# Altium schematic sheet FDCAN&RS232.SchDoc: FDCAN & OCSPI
size A4; Date: Not used; ApprovedBy: Not used; CheckedBy: Not used; Author: Not used; CompanyName: STMicroelectronics; DrawnBy: Not used; Engineer: Not used; Organization: Not used; Address1: Not used; Address2: Not used; Address3: Not used; Address4: Not used; DocumentNumber: Not used; Revision: Not used; SheetNumber: 15; SheetTotal: 23
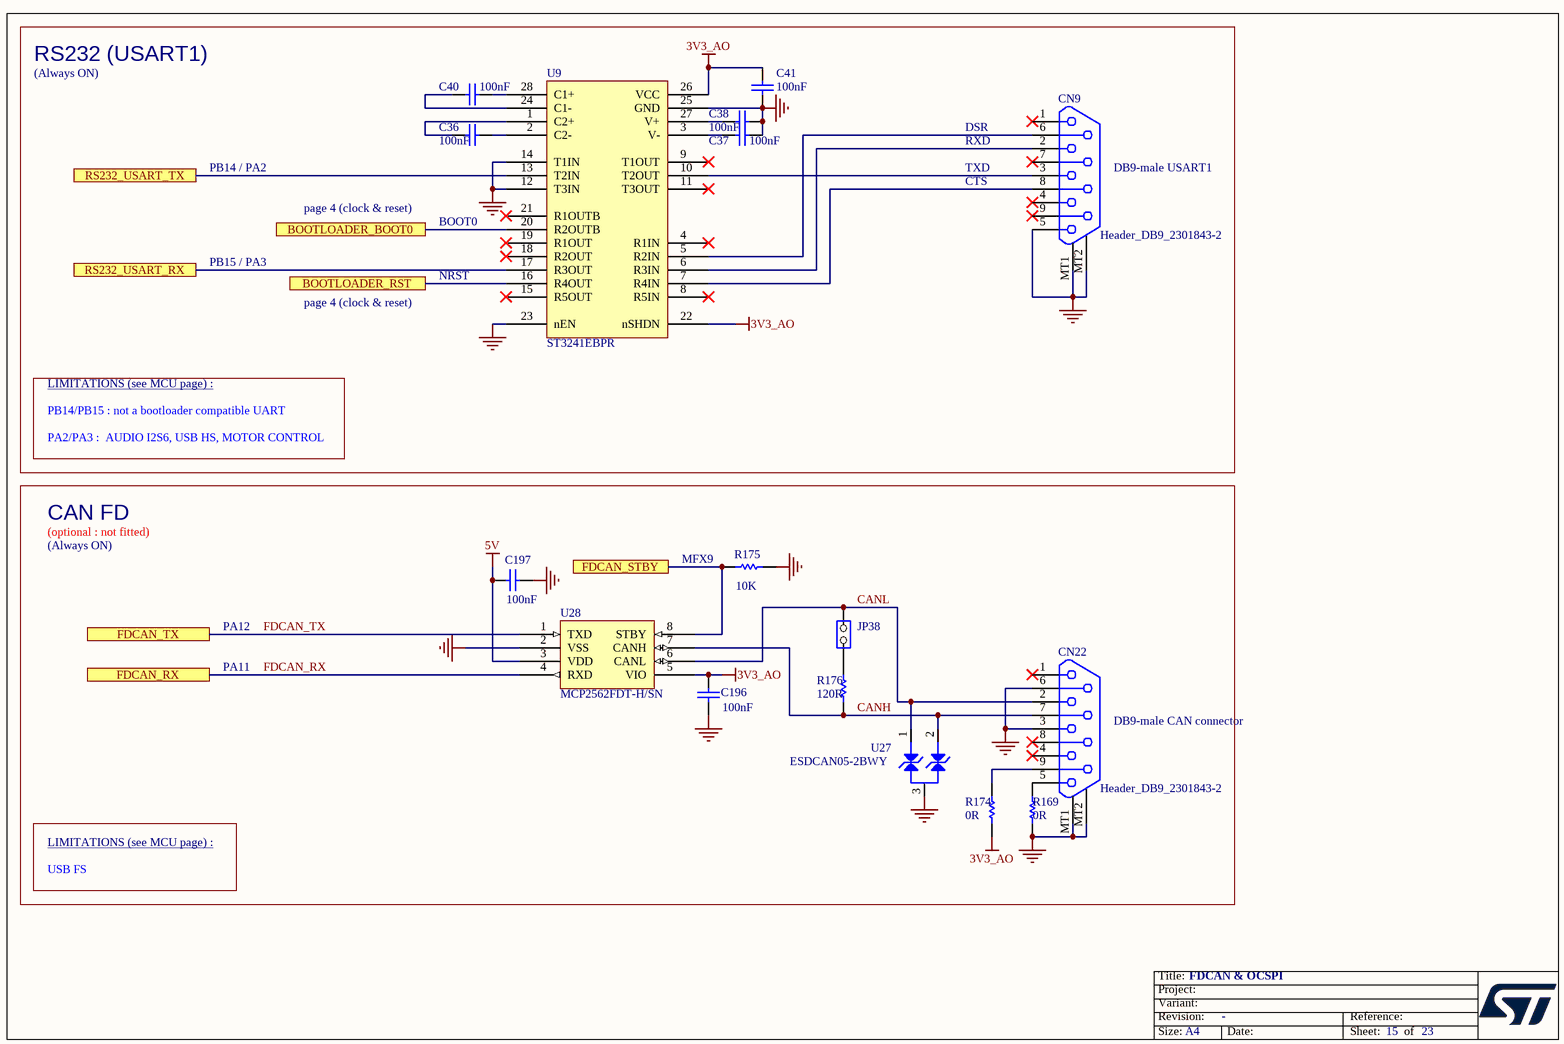
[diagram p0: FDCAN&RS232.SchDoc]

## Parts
C36  value 100nF  [C0402]  (hidden comment: Capacitor)
C37  value 100nF  [C0402]  (hidden comment: Capacitor)
C38  value 100nF  [C0402]  (hidden comment: Capacitor)
C40  value 100nF  [C0402]  (hidden comment: Capacitor)
C41  value 100nF  [C0402]  (hidden comment: Capacitor)
C196  value 100nF  [C0402]  (hidden comment: Capacitor)
C197  value 100nF  [C0402]  (hidden comment: Capacitor)
CN9  value Header_DB9_2301843-2  [CON_DB9-MALE_TYCO_2301843-2]  (hidden comment: DB9_Header_male_2301843-2)
CN22  value Header_DB9_2301843-2  [CON_DB9-MALE_TYCO_2301843-2]  (hidden comment: DB9_Header_male_2301843-2)
JP38  Jumper_Header 2x1  [CON_SAMTEC_TSW-102-07-G-S]  (value not drawn)
R169  value 0R  [R0603]  (hidden comment: Resistor)
R174  value 0R  [R0603]  (hidden comment: Resistor)
R175  value 10K  [R0402]  (hidden comment: Resistor)
R176  value 120R  [R0402]  (hidden comment: Resistor)
U9  ST3241EBPR  [ICC_SSOP28_10P2X5P3_P065]
U27  value ESDCAN05-2BWY  [DIO_SOT323]  (hidden comment: ESD-TRANSIL-DUAL-BIDIR)
U28  value MCP2562FDT-H/SN  [ICC_SO8_5X4_P127]  (hidden comment: MCP2562FD)

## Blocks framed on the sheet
RS232 (USART1): C36-C38 C40 C41 CN9 U9
CAN FD: C196 C197 CN22 JP38 R169 R174-R176 U27 U28

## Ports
BOOTLOADER_BOOT0, BOOTLOADER_RST, FDCAN_RX, FDCAN_STBY, FDCAN_TX, RS232_USART_RX, RS232_USART_TX

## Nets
3V3_AO: C41.1 C196.1 R174.1 U9.22(nSHDN) U9.26(VCC) U28.5(VIO)
5V: C197.1 U28.3(VDD)
GND: C37.1 C38.1 C41.2 C196.2 C197.2 CN9.5 CN9.MT1 CN9.MT2 CN22.3 CN22.6 CN22.MT1 CN22.MT2 R169.1 R175.2 U9.12(T3IN) U9.14(T1IN) U9.23(nEN) U9.25(GND) U27.3 U28.2(VSS)
BOOTLOADER_BOOT0: U9.20(R2OUTB) ; port BOOTLOADER_BOOT0
BOOTLOADER_RST: U9.16(R4OUT) ; port BOOTLOADER_RST
CANH: CN22.7 R176.1 U27.2 U28.7(CANH)
CANL: CN22.2 JP38.2(NO) U27.1 U28.6(CANL)
FDCAN_RX: U28.4(RXD) ; port FDCAN_RX
FDCAN_STBY: R175.1 U28.8(STBY) ; port FDCAN_STBY
FDCAN_TX: U28.1(TXD) ; port FDCAN_TX
RS232_USART_RX: U9.17(R3OUT) ; port RS232_USART_RX
RS232_USART_TX: U9.13(T2IN) ; port RS232_USART_TX
NetC36_1: C36.1 U9.1(C2+)
NetC36_2: C36.2 U9.2(C2-)
NetC37_2: C37.2 U9.3(V-)
NetC38_2: C38.2 U9.27(V+)
NetC40_1: C40.1 U9.24(C1-)
NetC40_2: C40.2 U9.28(C1+)
NetCN9_2: CN9.2 U9.6(R3IN)
NetCN9_3: CN9.3 U9.10(T2OUT)
NetCN9_6: CN9.6 U9.5(R2IN)
NetCN9_8: CN9.8 U9.7(R4IN)
NetCN22_5: CN22.5 R169.2
NetCN22_9: CN22.9 R174.2
NetJP38_1: JP38.1(COMMON) R176.2

Not connected (* = marked no-connect by the designer): CN9 1* 4* 7* 9*; CN22 1* 4* 8*; U9 4(R1IN)* 8(R5IN)* 9(T1OUT)* 11(T3OUT)* 15(R5OUT)* 18(R2OUT)* 19(R1OUT)* 21(R1OUTB)*

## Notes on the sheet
- (Always ON)
- PB14 / PA2
- RXD
- TXD
- CTS
- DSR
- (near CN9) DB9-male USART1
- page 4 (clock & reset)
- BOOT0
- PB15 / PA3
- NRST
- LIMITATIONS (see MCU page) :
- PB14/PB15 : not a bootloader compatible UART
- PA2/PA3 :  AUDIO I2S6, USB HS, MOTOR CONTROL
- (optional : not fitted)
- (near R175) MFX9
- PA12
- PA11
- (near CN22) DB9-male CAN connector
- USB FS

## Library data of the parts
C36-C38 C40 C41 C196 C197 = MCD-00006: Capacitor, MLCC, 100nF, 16V, X7R, 10%, 0402, T=0.5mm; Manufacturer_Part_Number: CC0402KRX7R7BB104; Manufacturer: YAGEO; Alternate_Manufacturer_Part_Number: GCM155R71C104KA55D; Alternate_Manufacturer: MURATA; Part_Preference: Recommended; Partial_Alternate_Internal_Part_Number: MCD-03299; Provided_By: SUBCO; ECCN_US: EAR99; ECCN_EU: NEC; Component_Country_Of_Origin: China; ID: 2474; Order_Code_RS: 9402047; ShowFields: YES
CN9 CN22 = MCD-01978: DB9_Male, RA, TH, height 13.575mm/3.8mm; Part_Type: Connector; Manufacturer: TE CONNECTIVITY; Part_Preference: Recommended; ECCN_US: EAR99; ECCN_EU: NEC; Provided_By: SUBCO; Component_Country_Of_Origin: China; ID: 4078; ShowFields: YES
JP38 = MCD-00045: Header, 2x1, 2,54mm, VR, TH, Height 5.84mm/2.54mm; Manufacturer_Part_Number: TSW-102-07-G-S; Manufacturer: SAMTEC; Part_Type: Connector; Alternate_Manufacturer_Part_Number: 313102S111116;313102S111116; Alternate_Manufacturer: JIUBABA; LIANYI; Full_Alternate_Internal_Part_Number: MCD-02390; Part_Preference: Recommended; Partial_Alternate_Internal_Part_Number: MCD-02957, MCD-03720; Provided_By: SUBCO; Component_Country_Of_Origin: China, Costa Rica, Malaysia, USA, Vietnam; ID: 2545; Order_Code_RS: 2505044; ShowFields: YES
R169 R174 = MCD-00056: Resistor,0R,0603,5%,1/10W; Manufacturer_Part_Number: RC0603JR-070RL; Manufacturer: YAGEO; Part_Preference: Recommended; Provided_By: SUBCO; ECCN_US: EAR99; ECCN_EU: NEC; Component_Country_Of_Origin: China; ID: 2536; Order_Code_RS: 9233130RL; ShowFields: YES
R175 = MCD-00053: Resistor,10K,0402,1%,1/16W; Manufacturer_Part_Number: RC0402FR-0710KL; Manufacturer: YAGEO; BMS_Part_Number: 9131590; Part_Preference: Recommended; Provided_By: SUBCO; ECCN_US: EAR99; ECCN_EU: NEC; Component_Country_Of_Origin: China; ID: 2539; Order_Code_RS: 9239359; ShowFields: YES
R176 = MCD-00194: Resistor,120R,0402,1%,1/16W; Manufacturer_Part_Number: RC0402FR-07120RL; Manufacturer: YAGEO; Part_Preference: Recommended; Provided_By: SUBCO; ECCN_US: EAR99; ECCN_EU: NEC; Component_Country_Of_Origin: China; ID: 2674; ShowFields: YES
U9 = MCD-00152: RS-232 transceiver with auto-power-down; Part_Type: IC; Manufacturer: STMICROELECTRONICS; BMS_Part_Number: 9176312; Manufacturer_HQ_COO: EU; Part_Preference: Recommended; Provided_By: SUBCO with ST control; ECCN_US: EAR99; ECCN_EU: NEC; Component_Country_Of_Origin: Philippines; ID: 2718; Order_Code_RS: 880-5383; ShowFields: YES
U27 = MCD-01358: Automotive dual-line Transil, transient voltage suppressor (TVS) for CAN bus 36V. Compliant with interfaces in automotive: CAN-FD, LIN, FlexRay, MOST, SENT, USB; Part_Type: Diode; Manufacturer: STMICROELECTRONICS; BMS_Part_Number: 9179021; Manufacturer_HQ_COO: EU; Part_Preference: Recommended; Provided_By: SUBCO with ST control; ECCN_US: EAR99; ECCN_EU: NEC; Component_Country_Of_Origin: China; ID: 3458; Order_Code_RS: 190-7635; ShowFields: YES
U28 = MCD-00129: High-Speed CAN Flexible Data Rate Transceiver; Manufacturer: MICROCHIP; Part_Type: IC; Part_Preference: Recommended; Provided_By: SUBCO; ECCN_US: EAR99; ECCN_EU: NEC; Component_Country_Of_Origin: Unknown; ID: 2737; ShowFields: YES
